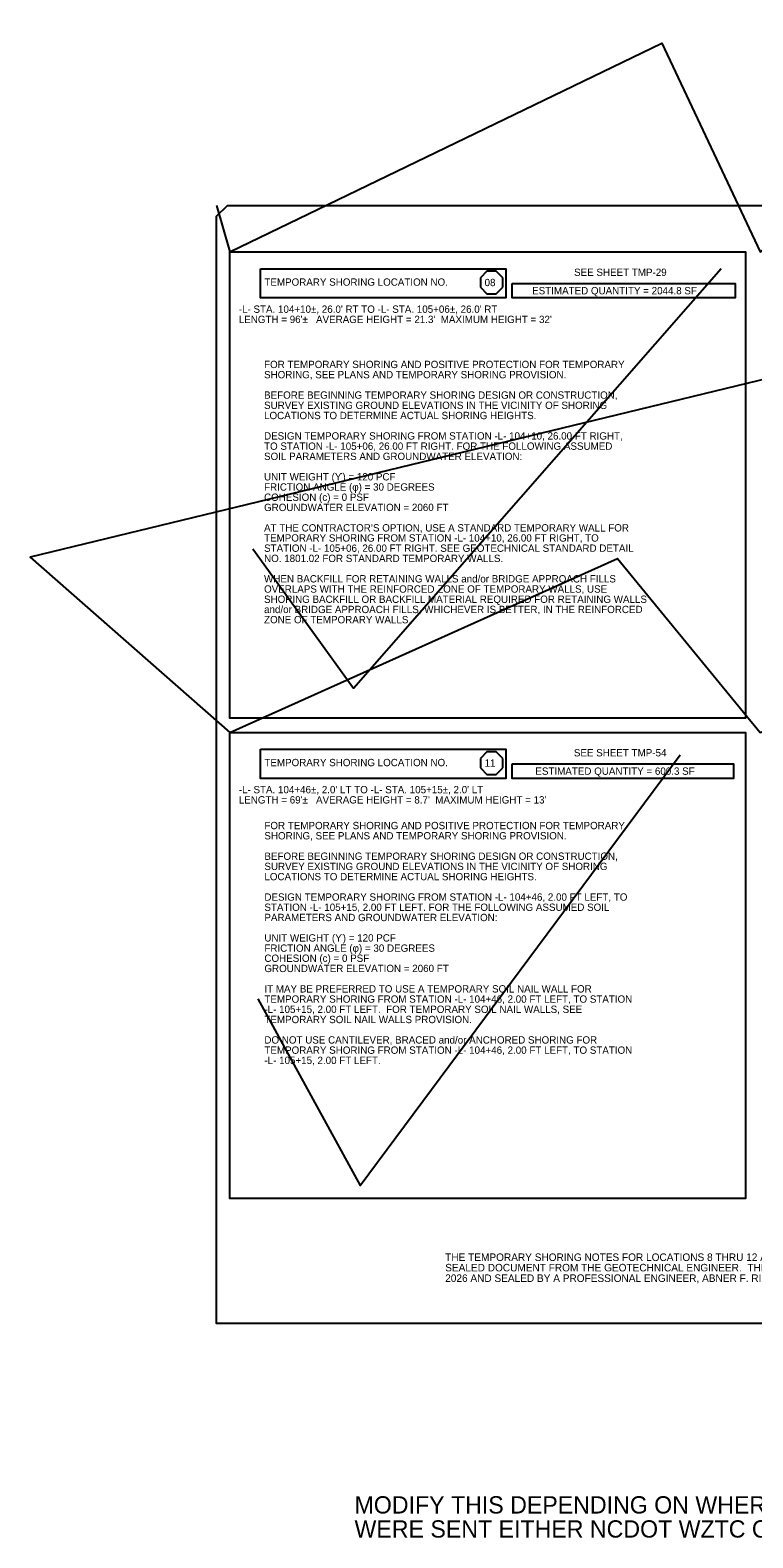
# Model space of a CAD drawing. Extents: x 2487012 to 2497594, y 369516 to 371986.
# Drawn here: x 2494163 to 2494835, y 370043 to 371445 of the extents above; entities that cross this region are included whole.
import ezdxf

# ---------------------------------------------------------------- set-up
doc = ezdxf.new("R2010")
doc.units = 0
for name, color, linetype in [('Scratch_Level_2', 7, 'Continuous'), ('Scratch_Level_3', 7, 'Continuous'), ('Scratch_Level_6', 7, 'Continuous'), ('TC LABEL TEMP SHORING', 7, 'Continuous'), ('TC SHEET BORDER LINE THIN', 7, 'Continuous'), ('TC SHEET LAYOUT SHAPE', 7, 'Continuous'), ('TC SHEET TEXT', 7, 'Continuous')]:
    doc.layers.add(name, color=color, linetype=linetype)

msp = doc.modelspace()

# ---------------------------------------------------------------- linework, layer by layer
at = {"layer": 'Scratch_Level_2'}
for points in [[(2494370.2, 370963), (2494463.5, 370833.5), (2494805.5, 371223.8)], [(2494374.8, 370544.5), (2494469.7, 370370.7), (2494767.4, 370771.5)]]:
    msp.add_lwpolyline(points, dxfattribs=at)
at = {"layer": 'Scratch_Level_3'}
msp.add_line((2494336.4, 371282.3), (2494336.4, 371282.3), dxfattribs=at)
at = {"layer": 'Scratch_Level_6'}
msp.add_lwpolyline([(2494336.4, 371282.3), (2494348.7, 371239.1), (2494750.3, 371433.4), (2494841.6, 371239.1), (2495156.4, 371445.4), (2495334.5, 371239.1), (2494163.1, 370955.2), (2494348.7, 370792.3), (2494709, 370953.9), (2494841.6, 370792.3), (2495197.6, 370924.6), (2495334.5, 370792.3)], dxfattribs=at)
at = {"layer": 'TC LABEL TEMP SHORING'}
for p, q in [((2494587.7, 371221.2), (2494581.6, 371215)), ((2494596.3, 371221.2), (2494587.7, 371221.2)), ((2494602.4, 371215), (2494596.3, 371221.2)), ((2494581.6, 371215), (2494581.6, 371206.3)), ((2494581.6, 371206.3), (2494587.7, 371200.1)), ((2494596.3, 371200.1), (2494602.4, 371206.3)), ((2494602.4, 371206.3), (2494602.4, 371215)), ((2494587.7, 371200.1), (2494596.3, 371200.1)), ((2494587.7, 370774.3), (2494581.6, 370768.1)), ((2494581.6, 370768.1), (2494581.6, 370759.4)), ((2494596.3, 370774.3), (2494587.7, 370774.3)), ((2494602.4, 370768.1), (2494596.3, 370774.3)), ((2494602.4, 370759.4), (2494602.4, 370768.1)), ((2494581.6, 370759.4), (2494587.7, 370753.2)), ((2494596.3, 370753.2), (2494602.4, 370759.4)), ((2494587.7, 370753.2), (2494596.3, 370753.2))]:
    msp.add_line(p, q, dxfattribs=at)
at = {"layer": 'TC SHEET BORDER LINE THIN'}
for points in [[(2494348.7, 371239.1), (2494828.1, 371239.1), (2494828.1, 370805.5), (2494348.7, 370805.5)], [(2494377.2, 371223.5), (2494605.2, 371223.5), (2494605.2, 371196.3), (2494377.2, 371196.3)], [(2494611, 371209.9), (2494818.5, 371209.9), (2494818.5, 371196.3), (2494611, 371196.3)], [(2494348.7, 370792.3), (2494828.1, 370792.3), (2494828.1, 370358.6), (2494348.7, 370358.6)], [(2494377.2, 370776.7), (2494605.2, 370776.7), (2494605.2, 370749.4), (2494377.2, 370749.4)], [(2494611, 370763), (2494816.8, 370763), (2494816.8, 370749.4), (2494611, 370749.4)]]:
    msp.add_lwpolyline(points, close=True, dxfattribs=at)
at = {"layer": 'TC SHEET LAYOUT SHAPE'}
msp.add_lwpolyline([(2494336.4, 370690.8), (2494336.4, 371000.2), (2494336.4, 371272.3), (2494346.4, 371282.3), (2494789.4, 371282.3), (2495260.4, 371282.3), (2495581.4, 371282.3), (2495581.4, 371202.3), (2495666.4, 371202.3), (2495666.4, 371250.3), (2495826.4, 371250.3), (2495826.4, 370915.3), (2495826.4, 370636.1), (2495826.4, 370384.8), (2495471.4, 370384.8), (2495471.4, 370242.3), (2495098.2, 370242.3), (2494928.7, 370242.3), (2494576, 370242.3), (2494336.4, 370242.3)], close=True, dxfattribs=at)

# ---------------------------------------------------------------- texts
at = {"layer": 'Scratch_Level_6'}
for s, p in [('MODIFY THIS DEPENDING ON WHERE THE SHORING RECOMMENDATIONS ', (2494464.6, 370065.7)), ('WERE SENT EITHER NCDOT WZTC OR STANTEC', (2494464.6, 370043.3))]:
    msp.add_text(s, height=16.094, dxfattribs=at).set_placement(p)
at = {"layer": 'TC LABEL TEMP SHORING'}
for s, p in [('08', (2494585.5, 371207.3)), ('11', (2494585.5, 370760.4))]:
    msp.add_text(s, height=6.81, dxfattribs=at).set_placement(p)
at = {"layer": 'TC SHEET BORDER LINE THIN'}
for s, p in [('FOR TEMPORARY SHORING AND POSITIVE PROTECTION FOR TEMPORARY ', (2494380.5, 371131.1)), ('SHORING, SEE PLANS AND TEMPORARY SHORING PROVISION.', (2494380.5, 371121.6)), ('BEFORE BEGINNING TEMPORARY SHORING DESIGN OR CONSTRUCTION, ', (2494380.5, 371102.6)), ('SURVEY EXISTING GROUND ELEVATIONS IN THE VICINITY OF SHORING ', (2494380.5, 371093.1)), ('LOCATIONS TO DETERMINE ACTUAL SHORING HEIGHTS.', (2494380.5, 371083.6)), ('DESIGN TEMPORARY SHORING FROM STATION -L- 104+10, 26.00 FT RIGHT, ', (2494380.5, 371064.6)), ('TO STATION -L- 105+06, 26.00 FT RIGHT. FOR THE FOLLOWING ASSUMED ', (2494380.5, 371055.1)), ('SOIL PARAMETERS AND GROUNDWATER ELEVATION:', (2494380.5, 371045.6)), ('UNIT WEIGHT (ϒ) = 120 PCF', (2494380.5, 371026.6)), ('FRICTION ANGLE (φ) = 30 DEGREES', (2494380.5, 371017.1)), ('COHESION (c) = 0 PSF', (2494380.5, 371007.6)), ('GROUNDWATER ELEVATION = 2060 FT', (2494380.5, 370998.1)), ('AT THE CONTRACTOR’S OPTION, USE A STANDARD TEMPORARY WALL FOR ', (2494380.5, 370979.1)), ('TEMPORARY SHORING FROM STATION -L- 104+10, 26.00 FT RIGHT, TO ', (2494380.5, 370969.7)), ('STATION -L- 105+06, 26.00 FT RIGHT. SEE GEOTECHNICAL STANDARD DETAIL ', (2494380.5, 370960.2)), ('NO. 1801.02 FOR STANDARD TEMPORARY WALLS. ', (2494380.5, 370950.7)), ('WHEN BACKFILL FOR RETAINING WALLS and/or BRIDGE APPROACH FILLS ', (2494380.5, 370931.7)), ('OVERLAPS WITH THE REINFORCED ZONE OF TEMPORARY WALLS, USE ', (2494380.5, 370922.2)), ('SHORING BACKFILL OR BACKFILL MATERIAL REQUIRED FOR RETAINING WALLS ', (2494380.5, 370912.7)), ('and/or BRIDGE APPROACH FILLS, WHICHEVER IS BETTER, IN THE REINFORCED ', (2494380.5, 370903.2)), ('ZONE OF TEMPORARY WALLS.', (2494380.5, 370893.7)), ('SHORING, SEE PLANS AND TEMPORARY SHORING PROVISION.', (2494380.8, 370692.7)), ('FOR TEMPORARY SHORING AND POSITIVE PROTECTION FOR TEMPORARY ', (2494380.8, 370702.2)), ('SURVEY EXISTING GROUND ELEVATIONS IN THE VICINITY OF SHORING ', (2494380.8, 370664.2)), ('BEFORE BEGINNING TEMPORARY SHORING DESIGN OR CONSTRUCTION, ', (2494380.8, 370673.7)), ('LOCATIONS TO DETERMINE ACTUAL SHORING HEIGHTS.', (2494380.8, 370654.7)), ('DESIGN TEMPORARY SHORING FROM STATION -L- 104+46, 2.00 FT LEFT, TO ', (2494380.8, 370635.7)), ('STATION -L- 105+15, 2.00 FT LEFT. FOR THE FOLLOWING ASSUMED SOIL ', (2494380.8, 370626.2)), ('PARAMETERS AND GROUNDWATER ELEVATION:', (2494380.8, 370616.7)), ('UNIT WEIGHT (ϒ) = 120 PCF', (2494380.8, 370597.7)), ('COHESION (c) = 0 PSF', (2494380.8, 370578.8)), ('FRICTION ANGLE (φ) = 30 DEGREES', (2494380.8, 370588.2)), ('GROUNDWATER ELEVATION = 2060 FT', (2494380.8, 370569.3)), ('TEMPORARY SHORING FROM STATION -L- 104+46, 2.00 FT LEFT, TO STATION ', (2494380.8, 370540.8)), ('IT MAY BE PREFERRED TO USE A TEMPORARY SOIL NAIL WALL FOR', (2494380.8, 370550.3)), ('-L- 105+15, 2.00 FT LEFT.  FOR TEMPORARY SOIL NAIL WALLS, SEE ', (2494380.8, 370531.3)), ('TEMPORARY SOIL NAIL WALLS PROVISION.', (2494380.8, 370521.8)), ('DO NOT USE CANTILEVER, BRACED and/or ANCHORED SHORING FOR ', (2494380.8, 370502.8)), ('TEMPORARY SHORING FROM STATION -L- 104+46, 2.00 FT LEFT, TO STATION ', (2494380.8, 370493.3)), ('-L- 105+15, 2.00 FT LEFT.', (2494380.8, 370483.8))]:
    msp.add_text(s, height=6.814, dxfattribs=at).set_placement(p)
at = {"layer": 'TC SHEET TEXT'}
for s, height, p in [('SEE SHEET TMP-29', 6.814, (2494668.7, 371216.8)), ('TEMPORARY SHORING LOCATION NO.', 6.814, (2494380.8, 371207.7)), ('ESTIMATED QUANTITY = 2044.8 SF', 6.814, (2494629.7, 371199.7)), ("-L- STA. 104+10±, 26.0' RT TO -L- STA. 105+06±, 26.0' RT", 6.814, (2494357, 371182.5)), ("LENGTH = 96'±   AVERAGE HEIGHT = 21.3'  MAXIMUM HEIGHT = 32'", 6.814, (2494357, 371173)), ('TEMPORARY SHORING LOCATION NO.', 6.814, (2494380.8, 370760.8)), ('SEE SHEET TMP-54', 6.814, (2494668.5, 370769.9)), ('ESTIMATED QUANTITY = 600.3 SF', 6.814, (2494632.7, 370752.8)), ("-L- STA. 104+46±, 2.0' LT TO -L- STA. 105+15±, 2.0' LT", 6.814, (2494357, 370735.6)), ("LENGTH = 69'±   AVERAGE HEIGHT = 8.7'  MAXIMUM HEIGHT = 13'", 6.814, (2494357, 370726.1)), ('THE TEMPORARY SHORING NOTES FOR LOCATIONS 8 THRU 12 AS SHOWN ON THIS SHEET WERE PROVIDED THROUGH A ', 7, (2494548.9, 370300.6)), ('SEALED DOCUMENT FROM THE GEOTECHNICAL ENGINEER.  THE DOCUMENT WAS SUBMITTED IN A MEMO DATED MAY 6, ', 7, (2494548.9, 370290.9)), ('2026 AND SEALED BY A PROFESSIONAL ENGINEER, ABNER F. RIGGS, PE, LICENSE #14155.', 7, (2494548.9, 370281.1))]:
    msp.add_text(s, height=height, dxfattribs=at).set_placement(p)

doc.saveas('drawing.dxf')
